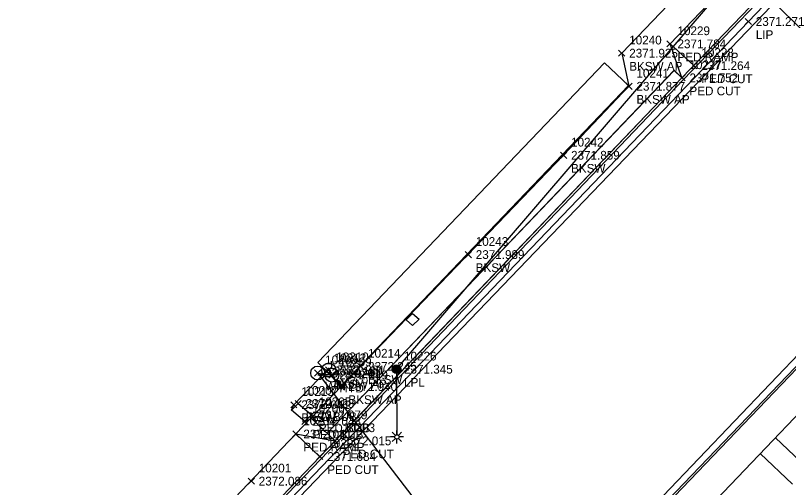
# Model space of a CAD drawing. Extents: x 2377639 to 2379738, y 729875 to 732734.
# Drawn here: x 2378522.8 to 2378700, y 730846.3 to 730954.4 of the extents above; entities that cross this region are included whole.
import ezdxf

# ---------------------------------------------------------------- set-up
doc = ezdxf.new("R2010")
doc.units = 0
for name, color, linetype in [('DES_ROADWAY_Sidewalk', 7, 'Continuous'), ('TOPO_CURBGTR_Back-of-Curb', 7, 'Continuous'), ('TOPO_CURBGTR_Face-of-Curb', 7, 'Continuous'), ('TOPO_CURBGTR_Lip-of-Gutter', 7, 'Continuous'), ('TOPO_DATA_Elevations', 7, 'Continuous'), ('TOPO_ELEC_Cable_Overhead-Exist', 7, 'Continuous'), ('TOPO_LIGHTING_Luminaire-Pole', 7, 'Continuous'), ('TOPO_LNDSCP_Misc', 7, 'Continuous'), ('TOPO_MISC_Flat-Asphalt', 7, 'Continuous'), ('TOPO_MISC_Mailbox', 7, 'Continuous'), ('TOPO_SW_Back', 7, 'Continuous'), ('TOPO_WTRUTIL_Fire-Hydrant', 7, 'Continuous'), ('TOPO_WTRUTIL_Line', 7, 'Continuous'), ('TOPO_WTRUTIL_Valve', 7, 'Continuous')]:
    doc.layers.add(name, color=color, linetype=linetype)

msp = doc.modelspace()

# ---------------------------------------------------------------- linework, layer by layer
at = {"layer": 'DES_ROADWAY_Sidewalk'}
for p, q in [((2378696.95, 730857.73), (2378704.31, 730850.68)), ((2378693.49, 730854.11), (2378700.85, 730847.06))]:
    msp.add_line(p, q, dxfattribs=at)
at = {"layer": 'TOPO_CURBGTR_Back-of-Curb'}
for points in [[(2378796.95, 731066.54), (2378792.22, 731061.65), (2378780.11, 731049.06), (2378765.8, 731034.16), (2378729.83, 730996.57), (2378708.78, 730974.71), (2378675.54, 730940.1), (2378596.07, 730857.01), (2378571.8, 730831.72), (2378484.65, 730740.78), (2378451.54, 730706.2), (2378383.47, 730635.07)], [(2378652.61, 730822.27), (2378656.41, 730826.17), (2378705.39, 730877.23), (2378739.19, 730912.58), (2378768.06, 730942.7), (2378799.37, 730975.36), (2378801.45, 730977.65), (2378842.1, 731019.83)]]:
    msp.add_lwpolyline(points, dxfattribs=at)
at = {"layer": 'TOPO_CURBGTR_Face-of-Curb'}
for points in [[(2378797.32, 731066.2), (2378792.58, 731061.31), (2378780.47, 731048.72), (2378766.16, 731033.81), (2378730.19, 730996.23), (2378709.14, 730974.36), (2378675.9, 730939.76), (2378596.44, 730856.66), (2378572.16, 730831.38), (2378485.01, 730740.44), (2378451.9, 730705.86), (2378383.83, 730634.72)], [(2378841.75, 731020.19), (2378801.08, 730977.99), (2378799.01, 730975.7), (2378767.7, 730943.05), (2378738.83, 730912.92), (2378705.03, 730877.57), (2378656.05, 730826.51), (2378652.25, 730822.61)]]:
    msp.add_lwpolyline(points, dxfattribs=at)
at = {"layer": 'TOPO_CURBGTR_Lip-of-Gutter'}
for points in [[(2378797.98, 731065.07), (2378794.67, 731061.59), (2378781.68, 731047.95), (2378751.07, 731015.98), (2378690.75, 730953), (2378584.09, 730841.86), (2378466.86, 730719.3), (2378390.08, 730639.26), (2378384.85, 730633.62), (2378384.85, 730633.62)], [(2378651.47, 730823.98), (2378654.91, 730827.35), (2378703.88, 730878.6), (2378754.22, 730930.91), (2378786.67, 730964.81), (2378838.98, 731019.71)]]:
    msp.add_lwpolyline(points, dxfattribs=at)
at = {"layer": 'TOPO_DATA_Elevations'}
for p, q in [((2378690.04, 730952.29), (2378691.45, 730953.71)), ((2378690.04, 730953.71), (2378691.45, 730952.29)), ((2378672.09, 730947.18), (2378673.51, 730948.59)), ((2378672.09, 730948.59), (2378673.51, 730947.18)), ((2378661.03, 730945.05), (2378662.45, 730946.46)), ((2378661.03, 730946.46), (2378662.45, 730945.05)), ((2378677.57, 730942.19), (2378678.98, 730943.6)), ((2378677.57, 730943.6), (2378678.98, 730942.19)), ((2378674.84, 730939.4), (2378676.25, 730940.81)), ((2378674.84, 730940.81), (2378676.25, 730939.4)), ((2378662.7, 730937.46), (2378664.11, 730938.88)), ((2378662.7, 730938.88), (2378664.11, 730937.46)), ((2378647.72, 730921.67), (2378649.13, 730923.09)), ((2378647.72, 730923.09), (2378649.13, 730921.67)), ((2378625.87, 730898.94), (2378627.29, 730900.35)), ((2378625.87, 730900.35), (2378627.29, 730898.94)), ((2378593.9, 730872.53), (2378595.32, 730873.95)), ((2378593.9, 730873.95), (2378595.32, 730872.53)), ((2378601.2, 730873.35), (2378602.62, 730874.77)), ((2378601.2, 730874.77), (2378602.62, 730873.35)), ((2378609.44, 730872.7), (2378610.86, 730874.12)), ((2378609.44, 730874.12), (2378610.86, 730872.7)), ((2378591.37, 730871.84), (2378592.78, 730873.25)), ((2378591.37, 730873.25), (2378592.78, 730871.84)), ((2378593.32, 730872.28), (2378594.73, 730873.7)), ((2378593.32, 730873.7), (2378594.73, 730872.28)), ((2378594.6, 730871.37), (2378596.01, 730872.79)), ((2378594.6, 730872.79), (2378596.01, 730871.37)), ((2378596.71, 730868.72), (2378598.12, 730870.14)), ((2378596.71, 730870.14), (2378598.12, 730868.72)), ((2378585.91, 730864.57), (2378587.32, 730865.98)), ((2378585.91, 730865.98), (2378587.32, 730864.57)), ((2378586.9, 730864.85), (2378588.31, 730866.27)), ((2378586.9, 730866.27), (2378588.31, 730864.85)), ((2378589.91, 730862.24), (2378591.32, 730863.66)), ((2378589.91, 730863.66), (2378591.32, 730862.24)), ((2378588.41, 730860.76), (2378589.83, 730862.17)), ((2378588.41, 730862.17), (2378589.83, 730860.76)), ((2378586.37, 730857.87), (2378587.79, 730859.28)), ((2378586.37, 730859.28), (2378587.79, 730857.87)), ((2378595.37, 730856.3), (2378596.78, 730857.71)), ((2378595.37, 730857.71), (2378596.78, 730856.3)), ((2378591.86, 730852.71), (2378593.28, 730854.12)), ((2378591.86, 730854.12), (2378593.28, 730852.71)), ((2378576.15, 730847.08), (2378577.57, 730848.5)), ((2378576.15, 730848.5), (2378577.57, 730847.08))]:
    msp.add_line(p, q, dxfattribs=at)
at = {"layer": 'TOPO_ELEC_Cable_Overhead-Exist'}
for p, q in [((2378610.15, 730873.41), (2378689.67, 730966.04)), ((2378819.66, 730833.88), (2378688.88, 730965.21))]:
    msp.add_line(p, q, dxfattribs=at)
at = {"layer": 'TOPO_LIGHTING_Luminaire-Pole'}
for p, q in [((2378610.15, 730873.41), (2378609.29, 730873.93)), ((2378610.15, 730873.41), (2378609.34, 730873.99)), ((2378610.15, 730873.41), (2378609.38, 730874.06)), ((2378610.15, 730873.41), (2378609.44, 730874.11)), ((2378610.15, 730873.41), (2378609.49, 730874.17)), ((2378610.15, 730873.41), (2378609.56, 730874.22)), ((2378610.15, 730873.41), (2378609.62, 730874.26)), ((2378610.15, 730873.41), (2378609.69, 730874.3)), ((2378610.15, 730873.41), (2378609.76, 730874.33)), ((2378610.15, 730873.41), (2378609.83, 730874.36)), ((2378610.15, 730873.41), (2378609.91, 730874.38)), ((2378610.15, 730873.41), (2378609.99, 730874.4)), ((2378610.15, 730873.41), (2378610.06, 730874.41)), ((2378610.15, 730873.41), (2378610.14, 730874.41)), ((2378610.15, 730873.41), (2378610.22, 730874.41)), ((2378610.15, 730873.41), (2378610.3, 730874.4)), ((2378610.15, 730873.41), (2378610.38, 730874.38)), ((2378610.15, 730873.41), (2378610.45, 730874.36)), ((2378610.15, 730873.41), (2378610.53, 730874.34)), ((2378610.15, 730873.41), (2378610.6, 730874.3)), ((2378610.15, 730873.41), (2378610.67, 730874.27)), ((2378610.15, 730873.41), (2378610.73, 730874.22)), ((2378610.15, 730873.41), (2378610.79, 730874.17)), ((2378610.15, 730873.41), (2378610.85, 730874.12)), ((2378610.15, 730873.41), (2378610.91, 730874.06)), ((2378610.15, 730873.41), (2378610.95, 730874)), ((2378610.15, 730873.41), (2378611, 730873.94)), ((2378610.15, 730873.41), (2378609.15, 730873.48)), ((2378610.15, 730873.41), (2378609.15, 730873.41)), ((2378610.15, 730873.41), (2378609.15, 730873.33)), ((2378610.15, 730873.41), (2378609.16, 730873.56)), ((2378610.15, 730873.41), (2378609.16, 730873.25)), ((2378610.15, 730873.41), (2378609.17, 730873.64)), ((2378610.15, 730873.41), (2378609.18, 730873.17)), ((2378610.15, 730873.41), (2378609.2, 730873.71)), ((2378610.15, 730873.41), (2378609.2, 730873.1)), ((2378610.15, 730873.41), (2378609.22, 730873.79)), ((2378610.15, 730873.41), (2378609.23, 730873.02)), ((2378610.15, 730873.41), (2378609.25, 730873.86)), ((2378610.15, 730873.41), (2378609.26, 730872.95)), ((2378610.15, 730873.41), (2378609.3, 730872.88)), ((2378610.15, 730873.41), (2378609.34, 730872.82)), ((2378610.15, 730873.41), (2378609.39, 730872.76)), ((2378610.15, 730873.41), (2378609.44, 730872.7)), ((2378610.15, 730873.41), (2378609.5, 730872.65)), ((2378610.15, 730873.41), (2378609.56, 730872.6)), ((2378610.15, 730873.41), (2378609.63, 730872.55)), ((2378610.15, 730873.41), (2378609.7, 730872.52)), ((2378610.15, 730873.41), (2378609.77, 730872.48)), ((2378610.15, 730873.41), (2378609.84, 730872.46)), ((2378610.15, 730873.41), (2378609.92, 730872.44)), ((2378610.15, 730873.41), (2378610, 730872.42)), ((2378610.15, 730873.41), (2378610.07, 730872.41)), ((2378610.15, 730873.41), (2378611.04, 730873.87)), ((2378610.15, 730873.41), (2378611.07, 730873.8)), ((2378610.15, 730873.41), (2378611.1, 730873.72)), ((2378610.15, 730873.41), (2378611.12, 730873.65)), ((2378610.15, 730873.41), (2378611.13, 730873.57)), ((2378610.15, 730873.41), (2378611.14, 730873.49)), ((2378610.15, 730873.41), (2378611.15, 730873.41)), ((2378610.15, 730873.41), (2378610.15, 730872.41)), ((2378610.15, 730873.41), (2378610.23, 730872.41)), ((2378610.15, 730873.41), (2378610.31, 730872.42)), ((2378610.15, 730873.41), (2378610.39, 730872.44)), ((2378610.15, 730873.41), (2378610.46, 730872.46)), ((2378610.15, 730873.41), (2378610.54, 730872.49)), ((2378610.15, 730873.41), (2378610.61, 730872.52)), ((2378610.15, 730873.41), (2378610.67, 730872.56)), ((2378610.15, 730873.41), (2378610.74, 730872.6)), ((2378610.15, 730873.41), (2378610.8, 730872.65)), ((2378610.15, 730873.41), (2378610.86, 730872.71)), ((2378610.15, 730873.41), (2378610.91, 730872.76)), ((2378610.15, 730873.41), (2378610.96, 730872.83)), ((2378610.15, 730873.41), (2378611, 730872.89)), ((2378610.15, 730873.41), (2378611.04, 730872.96)), ((2378610.15, 730873.41), (2378611.07, 730873.03)), ((2378610.15, 730873.41), (2378611.1, 730873.11)), ((2378610.15, 730873.41), (2378611.12, 730873.18)), ((2378610.15, 730873.41), (2378611.14, 730873.26)), ((2378610.15, 730873.41), (2378611.15, 730873.34)), ((2378610.15, 730872.91), (2378610.22, 730858.41)), ((2378609.16, 730858.97), (2378609.87, 730858.26)), ((2378610.22, 730858.41), (2378610.22, 730859.41)), ((2378610.57, 730858.27), (2378611.28, 730858.98)), ((2378609.72, 730857.91), (2378608.72, 730857.9)), ((2378609.17, 730856.84), (2378609.87, 730857.55)), ((2378610.23, 730856.41), (2378610.22, 730857.41)), ((2378610.58, 730857.56), (2378611.29, 730856.85)), ((2378611.72, 730857.92), (2378610.72, 730857.91))]:
    msp.add_line(p, q, dxfattribs=at)
for centre, radius in [((2378610.15, 730873.41), 1), ((2378610.22, 730857.91), 0.5)]:
    msp.add_circle(centre, radius, dxfattribs=at)
at = {"layer": 'TOPO_LNDSCP_Misc'}
msp.add_lwpolyline([(2378597.56, 730869.71), (2378663.27, 730938.35), (2378657.82, 730943.57), (2378592.1, 730874.93)], close=True, dxfattribs=at)
at = {"layer": 'TOPO_MISC_Flat-Asphalt'}
msp.add_lwpolyline([(2378594.27, 730858.74), (2378673.78, 730941.79), (2378675.54, 730940.1), (2378596.03, 730857.05)], close=True, dxfattribs=at)
at = {"layer": 'TOPO_MISC_Mailbox'}
msp.add_lwpolyline([(2378613.8, 730886.19), (2378615.31, 730884.89), (2378613.81, 730883.4), (2378612.31, 730884.7)], close=True, dxfattribs=at)
at = {"layer": 'TOPO_SW_Back'}
for p, q in [((2378672.8, 730947.88), (2378678.25, 730942.92)), ((2378675.54, 730940.1), (2378673.74, 730941.83)), ((2378587.08, 730858.58), (2378597.42, 730869.43)), ((2378596.07, 730857.01), (2378590.57, 730862.24)), ((2378589.12, 730861.46), (2378589.49, 730861.11)), ((2378587.08, 730858.58), (2378592.6, 730853.39))]:
    msp.add_line(p, q, dxfattribs=at)
for points in [[(2378850.53, 731003.91), (2378844.55, 731009.75), (2378842.49, 731009.62), (2378838.79, 731006.21), (2378801, 730966.3), (2378773.56, 730937.72), (2378746.11, 730909.08), (2378732.76, 730895.14), (2378711, 730872.44), (2378662.29, 730821.43), (2378657.01, 730815.99), (2378664.57, 730809.01)], [(2378675.54, 730940.1), (2378672.8, 730947.88), (2378700.36, 730976.64), (2378708.78, 730974.71)], [(2378691.61, 730967.51), (2378683.3, 730968.29), (2378674.15, 730958.76), (2378661.74, 730945.75), (2378663.4, 730938.17), (2378648.42, 730922.38)], [(2378673.74, 730941.83), (2378673.74, 730941.83), (2378594.27, 730858.74), (2378594.26, 730858.73)], [(2378586.11, 730864.07), (2378586.62, 730865.28), (2378594.02, 730872.99), (2378597.42, 730869.43), (2378648.42, 730922.38)], [(2378571.8, 730831.72), (2378569.96, 730840.68), (2378587.08, 730858.58), (2378596.07, 730857.01)]]:
    msp.add_lwpolyline(points, dxfattribs=at)
msp.add_lwpolyline([(2378587.61, 730865.56), (2378590.62, 730862.95), (2378589.12, 730861.46), (2378586.11, 730864.07)], close=True, dxfattribs=at)
at = {"layer": 'TOPO_WTRUTIL_Fire-Hydrant'}
for p, q in [((2378595.28, 730873.66), (2378595.26, 730875.25)), ((2378593.72, 730872.06), (2378592.14, 730872.03)), ((2378596.45, 730870.97), (2378597.6, 730869.85))]:
    msp.add_line(p, q, dxfattribs=at)
msp.add_circle((2378595.31, 730872.08), 1.6, dxfattribs=at)
at = {"layer": 'TOPO_WTRUTIL_Line'}
for p, q in [((2378391.81, 730640.09), (2378830.45, 731096.49)), ((2378592.08, 730872.54), (2378650.11, 730796.86)), ((2378592.08, 730872.54), (2378595.31, 730872.08))]:
    msp.add_line(p, q, dxfattribs=at)
at = {"layer": 'TOPO_WTRUTIL_Valve'}
for centre in [(2378592.08, 730872.54), (2378594.61, 730873.24)]:
    msp.add_circle(centre, 1.6, dxfattribs=at)

# ---------------------------------------------------------------- texts
at = {"layer": 'TOPO_DATA_Elevations'}
for s, p in [('2371.271', (2378692.45, 730952)), ('10229', (2378674.51, 730949.88)), ('LIP', (2378692.45, 730949)), ('10240', (2378663.45, 730947.75)), ('2371.784', (2378674.51, 730946.88)), ('2371.925', (2378663.45, 730944.75)), ('10228', (2378679.98, 730944.89)), ('PED RAMP', (2378674.51, 730943.88)), ('BKSW AP', (2378663.45, 730941.75)), ('10227', (2378677.25, 730942.1)), ('2371.264', (2378679.98, 730941.89)), ('10241', (2378665.11, 730940.17)), ('2371.752', (2378677.25, 730939.1)), ('PED CUT', (2378679.98, 730938.89)), ('2371.877', (2378665.11, 730937.17)), ('PED CUT', (2378677.25, 730936.1)), ('BKSW AP', (2378665.11, 730934.17)), ('10242', (2378650.13, 730924.38)), ('2371.859', (2378650.13, 730921.38)), ('BKSW', (2378650.13, 730918.38)), ('10243', (2378628.29, 730901.65)), ('2371.989', (2378628.29, 730898.65)), ('BKSW', (2378628.29, 730895.65)), ('10214', (2378603.62, 730876.06)), ('10226', (2378611.86, 730875.41)), ('10208', (2378593.78, 730874.54)), ('10212', (2378595.73, 730874.99)), ('10210', (2378596.32, 730875.24)), ('10209', (2378597.01, 730874.08)), ('2372.180', (2378595.73, 730871.99)), ('2371.981', (2378596.32, 730872.24)), ('2372.245', (2378603.62, 730873.06)), ('2371.345', (2378611.86, 730872.41)), ('2372.076', (2378593.78, 730871.54)), ('2372.049', (2378597.01, 730871.08)), ('10211', (2378599.12, 730871.43)), ('WMT', (2378593.78, 730868.54)), ('BKSW AP', (2378595.73, 730868.99)), ('WVL', (2378596.32, 730869.24)), ('2371.940', (2378599.12, 730868.43)), ('BKSW', (2378603.62, 730870.06)), ('LPL', (2378611.86, 730869.41)), ('10213', (2378588.32, 730867.28)), ('10207', (2378589.31, 730867.56)), ('HYD', (2378597.01, 730868.08)), ('10205', (2378592.32, 730864.95)), ('BKSW AP', (2378599.12, 730865.43)), ('2372.041', (2378588.32, 730864.28)), ('2372.128', (2378589.31, 730864.56)), ('10206', (2378590.83, 730863.46)), ('BKSW', (2378588.32, 730861.28)), ('PED BUB', (2378589.31, 730861.56)), ('2372.079', (2378592.32, 730861.95)), ('10204', (2378588.79, 730860.58)), ('2372.048', (2378590.83, 730860.46)), ('PED BUB', (2378592.32, 730858.95)), ('10203', (2378597.78, 730859.01)), ('2372.041', (2378588.79, 730857.58)), ('PED BUB', (2378590.83, 730857.46)), ('2372.015', (2378597.78, 730856.01)), ('PED RAMP', (2378588.79, 730854.58)), ('10202', (2378594.28, 730855.42)), ('2371.684', (2378594.28, 730852.42)), ('PED CUT', (2378597.78, 730853.01)), ('10201', (2378578.57, 730849.79)), ('PED CUT', (2378594.28, 730849.42)), ('2372.086', (2378578.57, 730846.79))]:
    msp.add_text(s, height=2, dxfattribs=at).set_placement(p)

doc.saveas('drawing.dxf')
